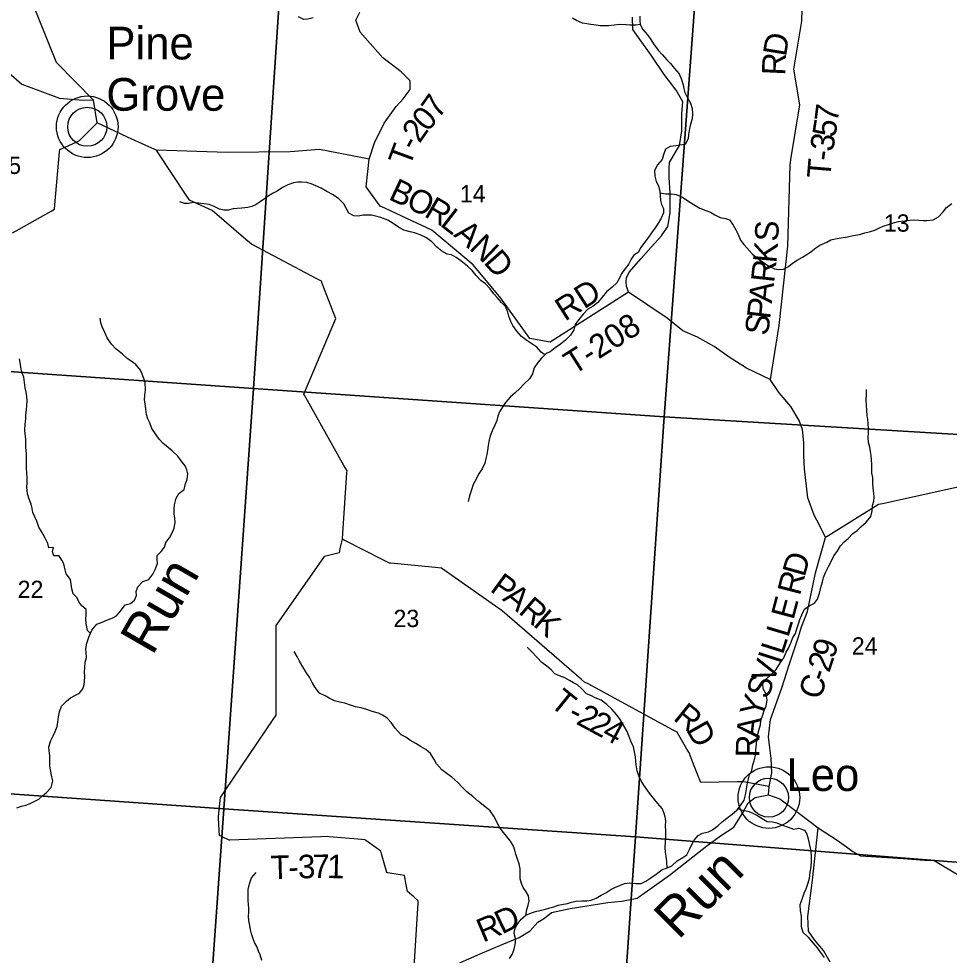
# Model space of a CAD drawing. Extents: x 1715311 to 2083412, y 146837 to 553079.
# Drawn here: x 1910925 to 1922803, y 416126 to 428080 of the extents above; entities that cross this region are included whole.
import ezdxf

# ---------------------------------------------------------------- set-up
doc = ezdxf.new("R2010")
doc.units = 0
for name, color, linetype in [('GM_X_County_Road', 7, 'Continuous'), ('GM_X_County_Road_Text', 7, 'Continuous'), ('GM_X_Minor_River', 7, 'Continuous'), ('GM_X_Minor_River_Text', 7, 'Continuous'), ('GM_X_Section', 7, 'Continuous'), ('GM_X_Section_Text', 7, 'Continuous'), ('GM_X_Township_Road', 7, 'Continuous'), ('GM_X_Township_Road_Text', 7, 'Continuous'), ('GM_X_Unincorporated', 7, 'Continuous'), ('GM_X_Unincorporated_Location', 7, 'Continuous'), ('GM_X_Unincorporated_Text', 7, 'Continuous')]:
    doc.layers.add(name, color=color, linetype=linetype)

msp = doc.modelspace()

# ---------------------------------------------------------------- linework, layer by layer
at = {"layer": 'GM_X_County_Road'}
for points in [[(1920494, 418173), (1920504, 418279), (1920540, 418454), (1920530, 418636), (1920515, 418775), (1920495, 418913), (1920523, 419137), (1920666, 419538), (1920759, 419834), (1920874, 420180), (1920918, 420318), (1920993, 420514), (1921094, 421009), (1921222, 421457), (1921149, 421614), (1921077, 421744), (1920998, 421966), (1920954, 422337), (1920947, 422501), (1920947, 422673), (1920929, 422836), (1920888, 422952), (1920782, 423132), (1920630, 423307), (1920516, 423475), (1920217, 423622), (1920007, 423754), (1919801, 423897), (1919589, 424014), (1919403, 424098), (1919201, 424259), (1918710, 424589), (1918685, 424666), (1918680, 424718), (1918684, 424778), (1918722, 424850), (1918866, 425016), (1918999, 425166), (1919131, 425308), (1919209, 425430), (1919240, 425602), (1919240, 425859), (1919229, 426053), (1919227, 426169), (1919233, 426243), (1919281, 426327), (1919358, 426463), (1919388, 426649), (1919391, 426872), (1919403, 427018), (1919317, 427168), (1919166, 427367), (1919000, 427617), (1918856, 427810), (1918764, 427942), (1918759, 428102)], [(1924698, 422531), (1924685, 422525), (1924560, 422471), (1924488, 422451), (1924339, 422414), (1921952, 421889), (1921900, 421878), (1921855, 421850), (1921268, 421486), (1921222, 421457)], [(1916383, 415952), (1916814, 416143), (1917097, 416263), (1917313, 416355), (1917453, 416439), (1917551, 416547), (1917638, 416598), (1917724, 416672), (1917964, 416724), (1918445, 416799), (1918623, 416819), (1918821, 416857), (1919234, 417149), (1919709, 417522), (1919884, 417652), (1920052, 417762), (1920171, 417954), (1920235, 418074), (1920327, 418142), (1920494, 418173)], [(1920494, 418173), (1920641, 418122), (1920899, 417929), (1921128, 417755), (1921371, 417596), (1921491, 417509), (1921573, 417451), (1921669, 417395), (1922217, 417360), (1922487, 417339), (1922611, 417335), (1922919, 417152), (1923093, 416991), (1923649, 416622)], [(1921281, 416039), (1921196, 416188), (1921082, 416324), (1921008, 416435), (1920998, 416621), (1921059, 417085), (1921128, 417755)]]:
    msp.add_lwpolyline(points, dxfattribs=at)
at = {"layer": 'GM_X_Minor_River'}
for points in [[(1914684, 428091), (1914616, 428073), (1914564, 428069), (1914496, 428106)], [(1918854, 428115), (1918852, 428059), (1918859, 428008), (1918891, 427942), (1918953, 427874), (1918993, 427814), (1919027, 427760), (1919088, 427681), (1919144, 427619), (1919200, 427557), (1919244, 427507), (1919296, 427444), (1919356, 427376), (1919387, 427306), (1919407, 427238), (1919417, 427188), (1919429, 427138), (1919461, 427072), (1919502, 427003), (1919522, 426933), (1919526, 426865), (1919520, 426801), (1919501, 426733), (1919489, 426677), (1919475, 426601), (1919469, 426547), (1919432, 426477), (1919364, 426466), (1919312, 426458), (1919242, 426448), (1919182, 426414), (1919154, 426342), (1919137, 426283), (1919081, 426215), (1919039, 426141), (1919044, 426069), (1919064, 426003), (1919092, 425949), (1919108, 425876), (1919112, 425824), (1919117, 425760), (1919131, 425708), (1919155, 425658), (1919157, 425602), (1919125, 425534), (1919082, 425464), (1919050, 425412), (1919004, 425349), (1918955, 425281), (1918913, 425225), (1918865, 425159), (1918831, 425097), (1918776, 425063), (1918744, 425011), (1918714, 424953), (1918674, 424900), (1918619, 424828), (1918599, 424776), (1918561, 424708), (1918499, 424652), (1918430, 424596), (1918374, 424527), (1918318, 424459), (1918256, 424411), (1918189, 424375), (1918129, 424309), (1918075, 424240), (1918026, 424178), (1918010, 424108), (1917968, 424040), (1917904, 423976), (1917839, 423928), (1917773, 423881), (1917709, 423827), (1917659, 423807), (1917599, 423749), (1917552, 423691), (1917506, 423623), (1917482, 423549), (1917445, 423482), (1917377, 423420), (1917319, 423356), (1917267, 423308), (1917200, 423250), (1917140, 423183), (1917106, 423131), (1917063, 423061), (1917043, 423007), (1917027, 422951)], [(1918859, 428008), (1918801, 427999), (1918727, 427999), (1918677, 428001), (1918589, 428006), (1918527, 428000), (1918455, 427990), (1918349, 427990), (1918295, 427997), (1918227, 428007), (1918175, 428017), (1918123, 428023), (1918047, 428058), (1917995, 428088)], [(1917641, 423790), (1917595, 423825), (1917537, 423887), (1917475, 423932), (1917409, 423972), (1917345, 424026), (1917282, 424093), (1917234, 424165), (1917208, 424215), (1917182, 424285), (1917168, 424335), (1917137, 424407), (1917087, 424460), (1917033, 424520), (1916989, 424570), (1916941, 424632), (1916883, 424696), (1916824, 424741), (1916766, 424803), (1916712, 424867), (1916654, 424923), (1916570, 424990), (1916510, 425034), (1916448, 425068), (1916396, 425077), (1916326, 425113), (1916261, 425165), (1916197, 425233), (1916129, 425282), (1916051, 425320), (1915979, 425346), (1915921, 425359), (1915843, 425381), (1915775, 425421), (1915705, 425466), (1915635, 425508), (1915549, 425542), (1915481, 425560), (1915427, 425573), (1915373, 425575), (1915321, 425571), (1915259, 425561), (1915203, 425564), (1915137, 425598), (1915105, 425664), (1915076, 425718), (1915012, 425780), (1914940, 425833), (1914860, 425877), (1914784, 425919), (1914718, 425948), (1914660, 425974), (1914602, 425990), (1914540, 425996), (1914486, 425993), (1914432, 425985), (1914360, 425959), (1914294, 425927), (1914223, 425880), (1914173, 425852), (1914123, 425826), (1914061, 425782), (1914007, 425742), (1913955, 425707), (1913902, 425683), (1913850, 425669), (1913774, 425661), (1913712, 425659), (1913662, 425652), (1913600, 425638), (1913544, 425636), (1913490, 425648), (1913422, 425683), (1913356, 425707), (1913294, 425719), (1913222, 425727), (1913156, 425734), (1913092, 425722), (1913040, 425720), (1912982, 425742)], [(1919109, 425859), (1919186, 425844), (1919254, 425846), (1919316, 425838), (1919398, 425801), (1919468, 425757), (1919534, 425713), (1919621, 425662), (1919695, 425634), (1919755, 425610), (1919809, 425578), (1919879, 425543), (1919945, 425529), (1919999, 425513), (1920047, 425447), (1920079, 425386), (1920107, 425328), (1920140, 425252), (1920182, 425200), (1920224, 425150), (1920286, 425079), (1920354, 425021), (1920414, 424983), (1920487, 424930), (1920573, 424886), (1920623, 424878), (1920689, 424882), (1920752, 424919), (1920802, 424961), (1920860, 424997), (1920930, 425037), (1920984, 425069), (1921035, 425106), (1921099, 425156), (1921151, 425190), (1921239, 425230), (1921291, 425256), (1921346, 425271), (1921422, 425285), (1921504, 425297), (1921578, 425312), (1921658, 425328), (1921726, 425346), (1921798, 425364), (1921852, 425383), (1921905, 425405), (1921961, 425433), (1922041, 425459), (1922093, 425474), (1922157, 425490), (1922237, 425502), (1922299, 425510), (1922363, 425513), (1922417, 425507), (1922469, 425503), (1922519, 425503), (1922596, 425514), (1922666, 425550), (1922726, 425616), (1922770, 425672), (1922835, 425720)], [(1912023, 424075), (1911989, 424147), (1911975, 424199), (1911963, 424257)], [(1911230, 418162), (1911280, 418204), (1911341, 418266), (1911359, 418354), (1911347, 418406), (1911331, 418494), (1911322, 418546), (1911322, 418678), (1911314, 418736), (1911310, 418786), (1911333, 418866), (1911363, 418928), (1911389, 418982), (1911414, 419048), (1911426, 419102), (1911432, 419170), (1911446, 419232), (1911473, 419304), (1911535, 419368), (1911585, 419412), (1911641, 419440), (1911699, 419471), (1911742, 419525), (1911760, 419577), (1911764, 419627), (1911768, 419683), (1911766, 419739), (1911767, 419799), (1911775, 419869), (1911791, 419925), (1911787, 419985), (1911784, 420039), (1911794, 420109), (1911820, 420187), (1911860, 420275), (1911921, 420351), (1911989, 420379), (1912057, 420409), (1912119, 420428), (1912173, 420460), (1912236, 420534), (1912284, 420598), (1912352, 420618), (1912404, 420657), (1912427, 420719), (1912423, 420771), (1912445, 420827), (1912511, 420899), (1912586, 420921), (1912636, 420989), (1912666, 421051), (1912696, 421125), (1912691, 421177), (1912693, 421227), (1912743, 421282), (1912787, 421336), (1912801, 421394), (1912848, 421456), (1912882, 421520), (1912908, 421578), (1912921, 421652), (1912919, 421704), (1912911, 421762), (1912911, 421818), (1912915, 421874), (1912934, 421960), (1912970, 422022), (1913036, 422072), (1913050, 422132), (1913075, 422202), (1913083, 422272), (1913073, 422322), (1913049, 422372), (1913013, 422422), (1912956, 422496), (1912886, 422563), (1912834, 422607), (1912764, 422663), (1912718, 422714), (1912680, 422768), (1912623, 422852), (1912597, 422922), (1912573, 422974), (1912557, 423030), (1912546, 423098), (1912538, 423167), (1912530, 423217), (1912534, 423275), (1912542, 423343), (1912539, 423437), (1912521, 423487), (1912503, 423543), (1912479, 423593), (1912420, 423665), (1912362, 423708), (1912308, 423742), (1912248, 423798), (1912164, 423868), (1912108, 423927), (1912055, 424009), (1912023, 424075)], [(1911841, 420233), (1911802, 420273), (1911785, 420362), (1911783, 420418), (1911787, 420480), (1911785, 420538), (1911732, 420588), (1911692, 420638), (1911670, 420688), (1911620, 420738), (1911602, 420805), (1911594, 420865), (1911587, 420921), (1911531, 420993), (1911517, 421047), (1911499, 421121), (1911477, 421171), (1911440, 421226), (1911372, 421226), (1911356, 421276), (1911370, 421330), (1911310, 421328), (1911298, 421384), (1911260, 421458), (1911217, 421537), (1911183, 421591), (1911155, 421669), (1911131, 421721), (1911105, 421777), (1911098, 421827), (1911082, 421885), (1911058, 421950), (1911038, 422014), (1911029, 422102), (1911033, 422158), (1911035, 422212), (1911029, 422290), (1911023, 422340), (1911024, 422522), (1911016, 422610), (1911017, 422664), (1911015, 422714), (1911009, 422780), (1911005, 422832), (1911009, 422904), (1911014, 422974), (1911018, 423026), (1911024, 423088), (1911028, 423140), (1911033, 423202), (1911029, 423257), (1911021, 423315), (1911007, 423371), (1911001, 423435), (1910990, 423505), (1910968, 423555), (1910956, 423609), (1910946, 423665), (1910936, 423739)], [(1920215, 418249), (1920229, 418327), (1920241, 418379), (1920255, 418431), (1920283, 418491), (1920298, 418557), (1920314, 418609), (1920334, 418693), (1920336, 418747), (1920341, 418819), (1920345, 418877), (1920355, 418931), (1920377, 419013), (1920392, 419067), (1920400, 419123), (1920424, 419197), (1920442, 419251), (1920465, 419311), (1920479, 419381), (1920465, 419459), (1920427, 419525), (1920424, 419597), (1920470, 419655), (1920524, 419705), (1920592, 419775), (1920651, 419863), (1920693, 419921), (1920723, 419995), (1920750, 420048), (1920786, 420122), (1920808, 420182), (1920840, 420234), (1920859, 420292), (1920879, 420356), (1920895, 420412), (1920921, 420472), (1920956, 420546), (1921016, 420588), (1921084, 420622), (1921122, 420673), (1921149, 420749), (1921163, 420819), (1921185, 420893), (1921199, 420949), (1921224, 421011), (1921260, 421087), (1921298, 421161), (1921331, 421223), (1921371, 421281), (1921417, 421351), (1921463, 421405), (1921514, 421448), (1921572, 421508), (1921626, 421546), (1921676, 421596), (1921744, 421656), (1921801, 421725), (1921819, 421799), (1921823, 421867), (1921842, 421923), (1921846, 421973), (1921842, 422025), (1921830, 422089), (1921826, 422152), (1921827, 422224), (1921815, 422280), (1921813, 422332), (1921813, 422396), (1921809, 422452), (1921806, 422504), (1921800, 422556), (1921790, 422610), (1921772, 422670), (1921767, 422734), (1921771, 422794), (1921771, 422844), (1921767, 422912), (1921763, 422966), (1921756, 423016), (1921752, 423080), (1921748, 423148), (1921742, 423215), (1921749, 423281), (1921745, 423347)], [(1917027, 422951), (1917003, 422891), (1916967, 422819), (1916942, 422755), (1916928, 422683), (1916916, 422631), (1916908, 422569), (1916901, 422519), (1916889, 422467), (1916873, 422409), (1916841, 422335), (1916794, 422267), (1916766, 422203), (1916724, 422134), (1916703, 422068), (1916679, 421992), (1916661, 421920)], [(1919201, 417242), (1919198, 417321), (1919188, 417393), (1919181, 417443), (1919177, 417497), (1919183, 417577), (1919185, 417643), (1919186, 417717), (1919180, 417773), (1919184, 417841), (1919176, 417893), (1919162, 417949), (1919137, 418001), (1919083, 418064), (1919029, 418130), (1918979, 418194), (1918935, 418256), (1918898, 418311), (1918868, 418363), (1918840, 418417), (1918820, 418481), (1918810, 418531), (1918803, 418599), (1918797, 418659), (1918787, 418721), (1918771, 418787), (1918737, 418860), (1918712, 418926), (1918692, 418984), (1918662, 419034), (1918634, 419084), (1918604, 419134), (1918555, 419199), (1918497, 419267), (1918431, 419327), (1918359, 419381), (1918283, 419414), (1918229, 419440), (1918173, 419464), (1918111, 419532), (1918059, 419579), (1918008, 419605), (1917956, 419635), (1917898, 419669), (1917826, 419694), (1917770, 419720), (1917720, 419770), (1917668, 419816), (1917604, 419863), (1917542, 419925), (1917478, 419993), (1917417, 420058)], [(1917398, 416639), (1917410, 416709), (1917427, 416765), (1917441, 416821), (1917433, 416887), (1917403, 416938), (1917365, 416992), (1917345, 417042), (1917328, 417102), (1917326, 417170), (1917324, 417230), (1917312, 417294), (1917293, 417352), (1917271, 417416), (1917257, 417468), (1917239, 417519), (1917203, 417583), (1917150, 417647), (1917096, 417713), (1917058, 417765), (1917024, 417838), (1916988, 417900), (1916941, 417972), (1916875, 418026), (1916793, 418087), (1916723, 418151), (1916647, 418211), (1916585, 418272), (1916529, 418330), (1916454, 418398), (1916396, 418444), (1916324, 418495), (1916256, 418571), (1916228, 418627), (1916181, 418701), (1916123, 418754), (1916063, 418788), (1915993, 418828), (1915919, 418873), (1915865, 418909), (1915805, 418939), (1915729, 419027), (1915678, 419098), (1915622, 419158), (1915570, 419192), (1915518, 419216), (1915438, 419239), (1915368, 419263), (1915298, 419283), (1915224, 419299), (1915160, 419320), (1915086, 419346), (1915026, 419358), (1914956, 419375), (1914888, 419409), (1914836, 419437), (1914764, 419473), (1914710, 419544), (1914669, 419610), (1914635, 419674), (1914605, 419724), (1914551, 419808), (1914511, 419879), (1914484, 419933), (1914442, 420005)], [(1910901, 418007), (1910959, 418029), (1911015, 418043), (1911070, 418063), (1911124, 418087), (1911180, 418118), (1911230, 418162)], [(1917188, 416084), (1917222, 416136), (1917250, 416206), (1917265, 416286), (1917265, 416340), (1917251, 416404), (1917257, 416458), (1917289, 416520), (1917340, 416586), (1917398, 416639), (1917470, 416669), (1917520, 416683), (1917578, 416699), (1917649, 416714), (1917705, 416732), (1917757, 416746), (1917813, 416766), (1917879, 416778), (1917931, 416787), (1917981, 416803), (1918039, 416817), (1918115, 416821), (1918175, 416822), (1918231, 416828), (1918298, 416854), (1918362, 416892), (1918418, 416924), (1918482, 416965), (1918534, 416991), (1918607, 417023), (1918657, 417043), (1918725, 417050), (1918803, 417042), (1918869, 417042), (1918929, 417074), (1918995, 417115), (1919063, 417163), (1919138, 417219), (1919192, 417239), (1919262, 417266), (1919328, 417330), (1919401, 417376), (1919453, 417408), (1919487, 417478), (1919513, 417530), (1919547, 417594), (1919598, 417653), (1919654, 417683), (1919728, 417703), (1919780, 417727), (1919852, 417783), (1919905, 417830), (1919965, 417878), (1920031, 417926), (1920097, 417982), (1920138, 418036), (1920184, 418105), (1920204, 418175), (1920215, 418249)], [(1920107, 417995), (1920169, 417979), (1920231, 417965), (1920289, 417945), (1920349, 417913), (1920417, 417874), (1920479, 417834), (1920549, 417828), (1920603, 417816), (1920675, 417785), (1920745, 417761), (1920817, 417735), (1920883, 417748), (1920957, 417722), (1920987, 417672), (1921003, 417612), (1921019, 417532), (1921036, 417460), (1921042, 417388), (1921042, 417338), (1921036, 417257), (1921025, 417185), (1921015, 417105), (1920997, 417046), (1920972, 416968), (1920948, 416914), (1920920, 416838), (1920894, 416768), (1920899, 416692), (1920915, 416624), (1920915, 416560), (1920913, 416493), (1920934, 416423), (1921004, 416357), (1921062, 416287), (1921116, 416220), (1921156, 416166), (1921207, 416100)], [(1914027, 416060), (1914007, 416130), (1913987, 416180), (1913965, 416238), (1913934, 416288), (1913912, 416347), (1913896, 416401), (1913884, 416451), (1913874, 416507), (1913863, 416569), (1913857, 416625), (1913863, 416675), (1913863, 416725), (1913859, 416775), (1913856, 416827), (1913856, 416887), (1913854, 416965), (1913870, 417037), (1913895, 417113), (1913955, 417181)]]:
    msp.add_lwpolyline(points, dxfattribs=at)
at = {"layer": 'GM_X_Section'}
for points in [[(1908945, 429078), (1914281, 428745), (1913920, 423360), (1908594, 423731)], [(1914281, 428745), (1919561, 428339), (1919164, 422999), (1913920, 423360)], [(1919561, 428339), (1925145, 428119), (1925090, 427469), (1924698, 422716), (1924694, 422668), (1919164, 422999)], [(1908594, 423731), (1913920, 423360), (1913545, 417994), (1908259, 418367)], [(1913920, 423360), (1919164, 422999), (1918799, 417639), (1913545, 417994)], [(1919164, 422999), (1924694, 422668), (1924238, 417208), (1918799, 417639)], [(1908259, 418367), (1913545, 417994), (1913162, 412614), (1908000, 412975)], [(1913545, 417994), (1918799, 417639), (1918425, 412252), (1913162, 412614)], [(1918799, 417639), (1924238, 417208), (1924222, 417042), (1923755, 411935), (1922447, 411955), (1918425, 412252)]]:
    msp.add_lwpolyline(points, close=True, dxfattribs=at)
at = {"layer": 'GM_X_Township_Road'}
for points in [[(1920938, 428780), (1920916, 428051), (1920815, 427437), (1920890, 426981), (1920783, 426309)], [(1912585, 426446), (1912313, 426568), (1911926, 426753), (1911880, 427039), (1911407, 427521), (1911170, 428112), (1911025, 428471), (1911023, 428478)], [(1915400, 426286), (1915467, 426496), (1915589, 426748), (1915742, 426962), (1915832, 427056), (1915923, 427178), (1915921, 427286), (1915807, 427404), (1915575, 427583), (1915284, 427910), (1915228, 428062), (1915278, 428166)], [(1910657, 427508), (1910966, 427247), (1911229, 427145), (1911447, 427068), (1911697, 427046), (1911880, 427039)], [(1910844, 425348), (1910929, 425395), (1911339, 425625), (1911382, 425648), (1911386, 425704), (1911445, 426380), (1911448, 426410), (1911516, 426441), (1911659, 426506), (1911700, 426524), (1911741, 426566), (1911888, 426715), (1911926, 426753)], [(1918710, 424589), (1917711, 423953), (1917451, 423998), (1917081, 424513), (1916728, 424939), (1916199, 425382), (1915817, 425560), (1915600, 425661), (1915540, 425689), (1915361, 425936), (1915400, 426286), (1915139, 426340), (1914763, 426410), (1914390, 426380), (1913586, 426372), (1912685, 426401), (1912587, 426445), (1912585, 426446)], [(1920504, 418279), (1920453, 418288), (1920201, 418335), (1920178, 418339), (1920098, 418338), (1919635, 418331), (1919634, 418331), (1919596, 418426), (1919501, 418665), (1919486, 418704), (1919455, 418756), (1919352, 418934), (1919330, 418972), (1919278, 419000), (1918193, 419589), (1918148, 419613), (1918108, 419647), (1917096, 420521), (1917084, 420531), (1917012, 420581), (1916338, 421054), (1916320, 421066), (1916239, 421074), (1915676, 421129), (1915660, 421130), (1915583, 421169), (1915078, 421426), (1915058, 421437), (1915063, 421516), (1915114, 422286), (1915116, 422310), (1915077, 422379), (1914573, 423276), (1914566, 423288), (1914600, 423370), (1914961, 424223), (1914974, 424254), (1914948, 424319), (1914798, 424702), (1914788, 424729), (1914723, 424764), (1913905, 425199), (1913896, 425204), (1913826, 425264), (1913395, 425631), (1913394, 425633), (1913302, 425674), (1913114, 425758), (1913108, 425761), (1913055, 425841), (1912715, 426356), (1912685, 426401)], [(1920783, 426309), (1920783, 426308), (1920768, 426217), (1920737, 425179), (1920626, 424163), (1920516, 423475)], [(1915964, 415842), (1916022, 416792), (1916024, 416822), (1915967, 416872), (1915888, 416942), (1915888, 416942), (1915868, 417046), (1915859, 417098), (1915850, 417146), (1915794, 417155), (1915638, 417180), (1915624, 417182), (1915598, 417271), (1915554, 417423), (1915546, 417453), (1915486, 417497), (1915358, 417591), (1915348, 417599), (1915255, 417607), (1914887, 417640), (1914872, 417641), (1914781, 417638), (1913619, 417595), (1913612, 417595), (1913522, 417637), (1913488, 417653), (1913484, 417720), (1913475, 417879), (1913474, 417895), (1913483, 417984), (1913500, 418142), (1913500, 418142), (1913559, 418229), (1914183, 419148), (1914212, 419190), (1914212, 419245), (1914210, 420302), (1914210, 420334), (1914252, 420395), (1914828, 421218), (1914830, 421220), (1914929, 421246), (1914980, 421259), (1915018, 421268), (1915033, 421334), (1915046, 421385), (1915058, 421437)]]:
    msp.add_lwpolyline(points, dxfattribs=at)
at = {"layer": 'GM_X_Unincorporated'}
for centre, radius in [((1911800, 426701), 393), ((1911800, 426701), 249), ((1920501, 418139), 393), ((1920501, 418139), 249)]:
    msp.add_circle(centre, radius, dxfattribs=at)
at = {"layer": 'GM_X_Unincorporated_Location'}
for p, q in [((1911800, 426701), (1911800, 426701)), ((1920501, 418139), (1920501, 418139))]:
    msp.add_line(p, q, dxfattribs=at)

# ---------------------------------------------------------------- texts
at = {"layer": 'GM_X_County_Road_Text'}
for s, rotation, p in [('D', 74.3803, (1920957, 420944)), ('R', 75.5785, (1920896, 420707)), ('E', 75.1007, (1920814, 420397)), ('L', 73.4045, (1920748, 420173)), ('L', 72.3144, (1920678, 419953)), ('9', 71.9678, (1921329, 419899)), ('I', 72.2314, (1920640, 419835)), ('2', 71.6446, (1921271, 419723)), ('V', 71.8823, (1920557, 419583)), ('C', 71.5282, (1921155, 419374)), ('-', 71.5361, (1921232, 419606)), ('S', 70.5868, (1920487, 419385)), ('Y', 71.8784, (1920406, 419135)), ('A', 83.6594, (1920380, 418889)), ('R', 89.4184, (1920378, 418651)), ('D', 25.6191, (1917092, 416390)), ('R', 22.9111, (1916851, 416287))]:
    msp.add_text(s, height=300, rotation=rotation, dxfattribs=at).set_placement(p)
at = {"layer": 'GM_X_Minor_River_Text'}
for height, rotation, p in [(500.1, 60.0036, (1912631, 419940)), (500, 45.0052, (1919343, 416314))]:
    msp.add_text('Run', height=height, rotation=rotation, dxfattribs=at).set_placement(p)
at = {"layer": 'GM_X_Section_Text'}
for s, p in [('15', (1910627, 426099)), ('14', (1916556, 425735)), ('13', (1921968, 425362)), ('22', (1910911, 420686)), ('23', (1915709, 420315)), ('24', (1921559, 419964))]:
    msp.add_text(s, height=221, rotation=0, dxfattribs=at).set_placement(p)
at = {"layer": 'GM_X_Township_Road_Text'}
for s, rotation, p in [('D', 80.673, (1920719, 427589)), ('R', 87.3879, (1920709, 427352)), ('7', 54.6408, (1916286, 426791)), ('0', 48.5791, (1916142, 426626)), ('7', 82.718, (1921378, 426748)), ('2', 55.158, (1916042, 426481)), ('5', 81.1781, (1921349, 426557)), ('-', 62.4505, (1915990, 426381)), ('3', 81.1707, (1921320, 426374)), ('T', 69.8492, (1915917, 426179)), ('T', 85.2762, (1921285, 426034)), ('-', 81.8313, (1921303, 426253)), ('B', 334.7582, (1915632, 425781)), ('O', 334.515, (1915854, 425676)), ('R', 329.6742, (1916087, 425565)), ('L', 322.3415, (1916291, 425446)), ('A', 319.7994, (1916466, 425311)), ('S', 87.5146, (1920619, 425232)), ('N', 316.2417, (1916664, 425144)), ('K', 84.9094, (1920595, 424954)), ('D', 311.3114, (1916850, 424967)), ('R', 83.8412, (1920568, 424703)), ('RD', 32.7368, (1917898, 424211)), ('A', 83.8186, (1920539, 424441)), ('P', 83.4985, (1920516, 424238)), ('T-208', 32.364, (1918007, 423527)), ('S', 81.6938, (1920486, 424027)), ('P', 323.8105, (1916928, 420782)), ('A', 320.9841, (1917088, 420665)), ('R', 319.3648, (1917292, 420500)), ('K', 319.2825, (1917479, 420339)), ('T', 321.0049, (1917690, 419319)), ('R', 320.958, (1919267, 419138)), ('-', 332.3364, (1917919, 419142)), ('2', 331.5798, (1918027, 419086)), ('2', 331.6611, (1918190, 418998)), ('4', 331.6708, (1918353, 418910)), ('D', 299.7142, (1919439, 419005)), ('T', 1.6587, (1914145, 417097)), ('3', 1.3688, (1914492, 417107)), ('7', 0.6609, (1914675, 417111)), ('1', 358.324, (1914857, 417113)), ('-', 1.6005, (1914369, 417103))]:
    msp.add_text(s, height=300, rotation=rotation, dxfattribs=at).set_placement(p)
at = {"layer": 'GM_X_Unincorporated_Text'}
for s, p in [('Pine', (1912044, 427561)), ('Grove', (1912044, 426906)), ('Leo', (1920725, 418224))]:
    msp.add_text(s, height=417, rotation=0, dxfattribs=at).set_placement(p)

doc.saveas('drawing.dxf')
